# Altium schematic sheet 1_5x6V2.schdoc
size 411 x 289 mm; Name: default420x297; Symbol: default420x297; Device: default420x297; Size: "A3"; Id: /; File: 5x6V2; Sheet: /; @Page No: 1; @Page Count: 2; @Schematic Name: 5x6V2; @Project Name: 5x6V2_Left; @Board Name: 5x6V2; @Update Date: 2025-07-02; @Create Time: 08:47:11; @Update Time: 22:16:19; @Page Name: 5x6V2; @Create Date: 2025-06-30
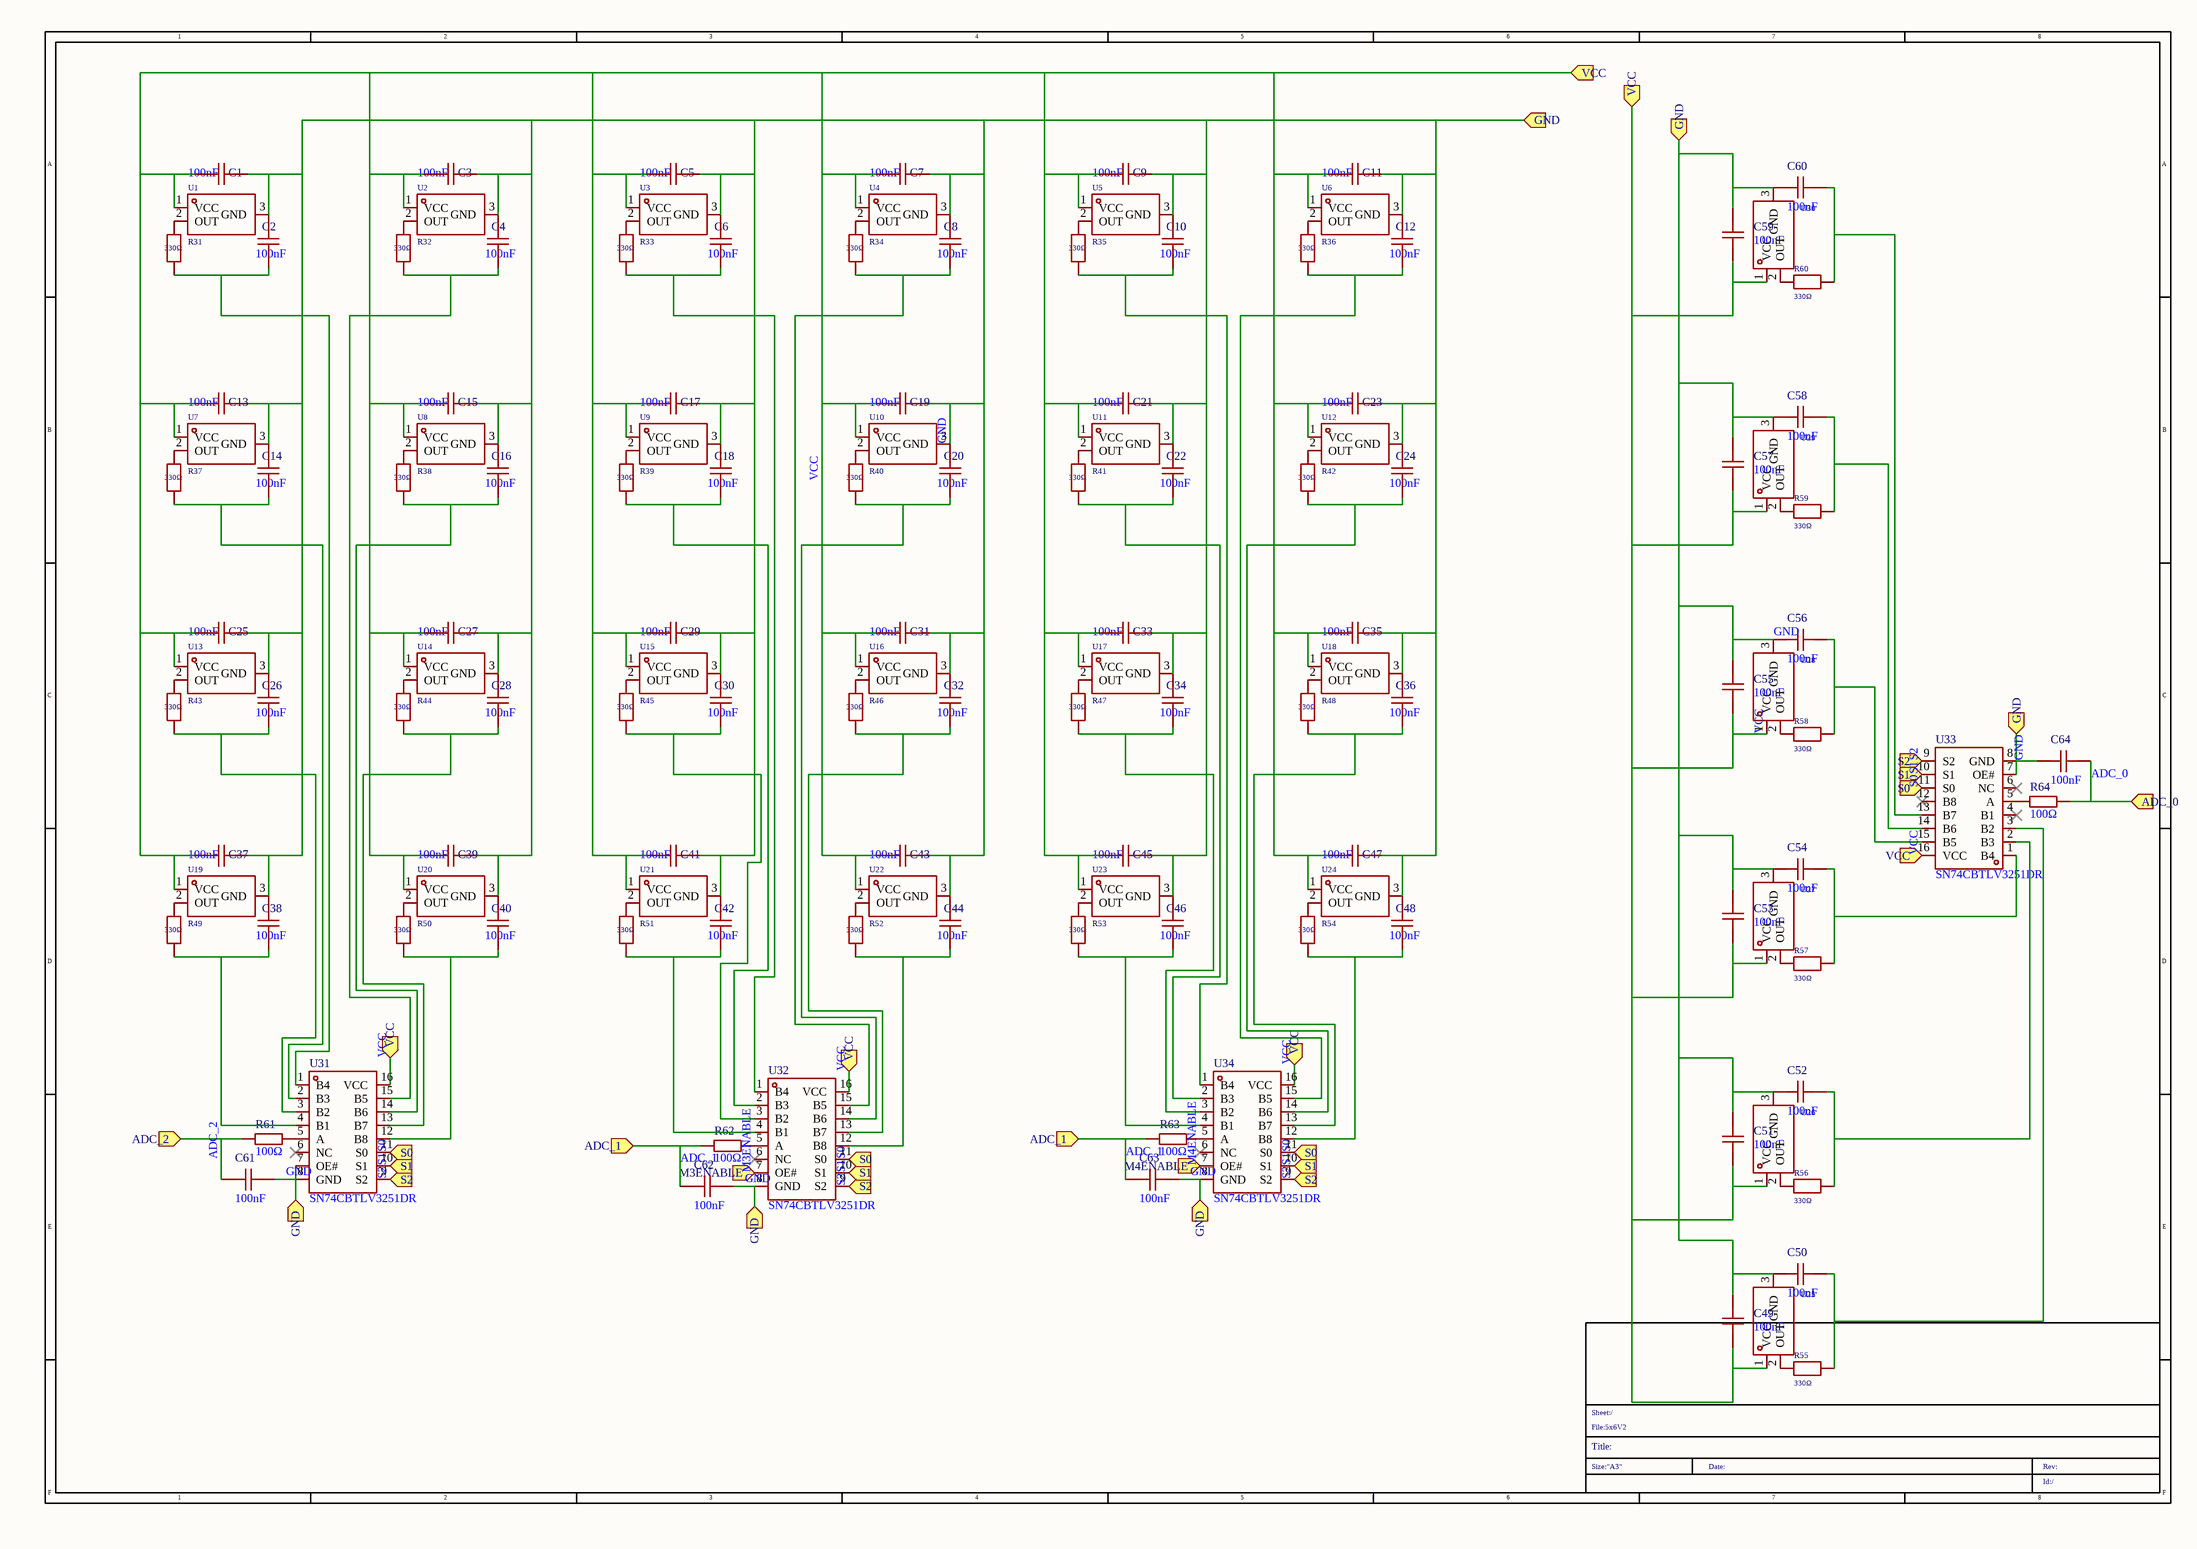
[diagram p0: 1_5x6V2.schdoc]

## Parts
C1  100nF  [C0805]
C2  100nF  [C0805]
C3  100nF  [C0805]
C4  100nF  [C0805]
C5  100nF  [C0805]
C6  100nF  [C0805]
C7  100nF  [C0805]
C8  100nF  [C0805]
C9  100nF  [C0805]
C10  100nF  [C0805]
C11  100nF  [C0805]
C12  100nF  [C0805]
C13  100nF  [C0805]
C14  100nF  [C0805]
C15  100nF  [C0805]
C16  100nF  [C0805]
C17  100nF  [C0805]
C18  100nF  [C0805]
C19  100nF  [C0805]
C20  100nF  [C0805]
C21  100nF  [C0805]
C22  100nF  [C0805]
C23  100nF  [C0805]
C24  100nF  [C0805]
C25  100nF  [C0805]
C26  100nF  [C0805]
C27  100nF  [C0805]
C28  100nF  [C0805]
C29  100nF  [C0805]
C30  100nF  [C0805]
C31  100nF  [C0805]
C32  100nF  [C0805]
C33  100nF  [C0805]
C34  100nF  [C0805]
C35  100nF  [C0805]
C36  100nF  [C0805]
C37  100nF  [C0805]
C38  100nF  [C0805]
C39  100nF  [C0805]
C40  100nF  [C0805]
C41  100nF  [C0805]
C42  100nF  [C0805]
C43  100nF  [C0805]
C44  100nF  [C0805]
C45  100nF  [C0805]
C46  100nF  [C0805]
C47  100nF  [C0805]
C48  100nF  [C0805]
C49  100nF  [C0805]
C50  100nF  [C0805]
C51  100nF  [C0805]
C52  100nF  [C0805]
C53  100nF  [C0805]
C54  100nF  [C0805]
C55  100nF  [C0805]
C56  100nF  [C0805]
C57  100nF  [C0805]
C58  100nF  [C0805]
C59  100nF  [C0805]
C60  100nF  [C0805]
C61  100nF  [C0805]
C62  100nF  [C0805]
C63  100nF  [C0805]
C64  100nF  [C0805]
R31  330Ω  [R1206]
R32  330Ω  [R1206]
R33  330Ω  [R1206]
R34  330Ω  [R1206]
R35  330Ω  [R1206]
R36  330Ω  [R1206]
R37  330Ω  [R1206]
R38  330Ω  [R1206]
R39  330Ω  [R1206]
R40  330Ω  [R1206]
R41  330Ω  [R1206]
R42  330Ω  [R1206]
R43  330Ω  [R1206]
R44  330Ω  [R1206]
R45  330Ω  [R1206]
R46  330Ω  [R1206]
R47  330Ω  [R1206]
R48  330Ω  [R1206]
R49  330Ω  [R1206]
R50  330Ω  [R1206]
R51  330Ω  [R1206]
R52  330Ω  [R1206]
R53  330Ω  [R1206]
R54  330Ω  [R1206]
R55  330Ω  [R1206]
R56  330Ω  [R1206]
R57  330Ω  [R1206]
R58  330Ω  [R1206]
R59  330Ω  [R1206]
R60  330Ω  [R1206]
R61  100Ω  [R0805]
R62  100Ω  [R0805]
R63  100Ω  [R0805]
R64  100Ω  [R0805]
U1  DRV5053VAQDBZR  [SOT-23-3_L2.9-W1.3-P1.90-LS2.4-BR]  (value not drawn)
U2  DRV5053VAQDBZR  [SOT-23-3_L2.9-W1.3-P1.90-LS2.4-BR]  (value not drawn)
U3  DRV5053VAQDBZR  [SOT-23-3_L2.9-W1.3-P1.90-LS2.4-BR]  (value not drawn)
U4  DRV5053VAQDBZR  [SOT-23-3_L2.9-W1.3-P1.90-LS2.4-BR]  (value not drawn)
U5  DRV5053VAQDBZR  [SOT-23-3_L2.9-W1.3-P1.90-LS2.4-BR]  (value not drawn)
U6  DRV5053VAQDBZR  [SOT-23-3_L2.9-W1.3-P1.90-LS2.4-BR]  (value not drawn)
U7  DRV5053VAQDBZR  [SOT-23-3_L2.9-W1.3-P1.90-LS2.4-BR]  (value not drawn)
U8  DRV5053VAQDBZR  [SOT-23-3_L2.9-W1.3-P1.90-LS2.4-BR]  (value not drawn)
U9  DRV5053VAQDBZR  [SOT-23-3_L2.9-W1.3-P1.90-LS2.4-BR]  (value not drawn)
U10  DRV5053VAQDBZR  [SOT-23-3_L2.9-W1.3-P1.90-LS2.4-BR]  (value not drawn)
U11  DRV5053VAQDBZR  [SOT-23-3_L2.9-W1.3-P1.90-LS2.4-BR]  (value not drawn)
U12  DRV5053VAQDBZR  [SOT-23-3_L2.9-W1.3-P1.90-LS2.4-BR]  (value not drawn)
U13  DRV5053VAQDBZR  [SOT-23-3_L2.9-W1.3-P1.90-LS2.4-BR]  (value not drawn)
U14  DRV5053VAQDBZR  [SOT-23-3_L2.9-W1.3-P1.90-LS2.4-BR]  (value not drawn)
U15  DRV5053VAQDBZR  [SOT-23-3_L2.9-W1.3-P1.90-LS2.4-BR]  (value not drawn)
U16  DRV5053VAQDBZR  [SOT-23-3_L2.9-W1.3-P1.90-LS2.4-BR]  (value not drawn)
U17  DRV5053VAQDBZR  [SOT-23-3_L2.9-W1.3-P1.90-LS2.4-BR]  (value not drawn)
U18  DRV5053VAQDBZR  [SOT-23-3_L2.9-W1.3-P1.90-LS2.4-BR]  (value not drawn)
U19  DRV5053VAQDBZR  [SOT-23-3_L2.9-W1.3-P1.90-LS2.4-BR]  (value not drawn)
U20  DRV5053VAQDBZR  [SOT-23-3_L2.9-W1.3-P1.90-LS2.4-BR]  (value not drawn)
U21  DRV5053VAQDBZR  [SOT-23-3_L2.9-W1.3-P1.90-LS2.4-BR]  (value not drawn)
U22  DRV5053VAQDBZR  [SOT-23-3_L2.9-W1.3-P1.90-LS2.4-BR]  (value not drawn)
U23  DRV5053VAQDBZR  [SOT-23-3_L2.9-W1.3-P1.90-LS2.4-BR]  (value not drawn)
U24  DRV5053VAQDBZR  [SOT-23-3_L2.9-W1.3-P1.90-LS2.4-BR]  (value not drawn)
U25  DRV5053VAQDBZR  [SOT-23-3_L2.9-W1.3-P1.90-LS2.4-BR]  (value not drawn)
U26  DRV5053VAQDBZR  [SOT-23-3_L2.9-W1.3-P1.90-LS2.4-BR]  (value not drawn)
U27  DRV5053VAQDBZR  [SOT-23-3_L2.9-W1.3-P1.90-LS2.4-BR]  (value not drawn)
U28  DRV5053VAQDBZR  [SOT-23-3_L2.9-W1.3-P1.90-LS2.4-BR]  (value not drawn)
U29  DRV5053VAQDBZR  [SOT-23-3_L2.9-W1.3-P1.90-LS2.4-BR]  (value not drawn)
U30  DRV5053VAQDBZR  [SOT-23-3_L2.9-W1.3-P1.90-LS2.4-BR]  (value not drawn)
U31  SN74CBTLV3251DR  [SOIC-16_L9.9-W3.9-P1.27-LS6.0-BL]
U32  SN74CBTLV3251DR  [SOIC-16_L9.9-W3.9-P1.27-LS6.0-BL]
U33  SN74CBTLV3251DR  [SOIC-16_L9.9-W3.9-P1.27-LS6.0-BL]
U34  SN74CBTLV3251DR  [SOIC-16_L9.9-W3.9-P1.27-LS6.0-BL]

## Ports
ADC_0 (in), ADC_1 (in), ADC_2 (in), GND (in), M3ENABLE (in), M4ENABLE (in), S0 (in), S1 (in), S2 (in), VCC (in)

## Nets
ADC_0: C64.1 R64.1 ; port ADC_0
ADC_1: C62.1 C63.1 R62.1 R63.1 ; port ADC_1
ADC_2: C61.1 R61.1 ; port ADC_2
GND: C1.2 C2.1 C3.2 C4.1 C5.2 C6.1 C7.2 C8.1 C9.2 C10.1 C11.2 C12.1 C13.2 C14.1 C15.2 C16.1 C17.2 C18.1 C19.2 C20.1 C21.2 C22.1 C23.2 C24.1 C25.2 C26.1 C27.2 C28.1 C29.2 C30.1 C31.2 C32.1 C33.2 C34.1 C35.2 C36.1 C37.2 C38.1 C39.2 C40.1 C41.2 C42.1 C43.2 C44.1 C45.2 C46.1 C47.2 C48.1 C49.2 C50.1 C51.2 C52.1 C53.2 C54.1 C55.2 C56.1 C57.2 C58.1 C59.2 C60.1 C61.2 C62.2 C63.2 C64.2 U1.3(GND) U2.3(GND) U3.3(GND) U4.3(GND) U5.3(GND) U6.3(GND) U7.3(GND) U8.3(GND) U9.3(GND) U10.3(GND) U11.3(GND) U12.3(GND) U13.3(GND) U14.3(GND) U15.3(GND) U16.3(GND) U17.3(GND) U18.3(GND) U19.3(GND) U20.3(GND) U21.3(GND) U22.3(GND) U23.3(GND) U24.3(GND) U25.3(GND) U26.3(GND) U27.3(GND) U28.3(GND) U29.3(GND) U30.3(GND) U31.7(OE#) U31.8(GND) U32.8(GND) U33.7(OE#) U33.8(GND) U34.8(GND) ; port GND
M3ENABLE: U32.7(OE#) ; port M3ENABLE
M4ENABLE: U34.7(OE#) ; port M4ENABLE
S0: U31.11(S0) U32.11(S0) U33.11(S0) U34.11(S0) ; port S0
S1: U31.10(S1) U32.10(S1) U33.10(S1) U34.10(S1) ; port S1
S2: U31.9(S2) U32.9(S2) U33.9(S2) U34.9(S2) ; port S2
VCC: C1.1 C3.1 C5.1 C7.1 C9.1 C11.1 C13.1 C15.1 C17.1 C19.1 C21.1 C23.1 C25.1 C27.1 C29.1 C31.1 C33.1 C35.1 C37.1 C39.1 C41.1 C43.1 C45.1 C47.1 C49.1 C51.1 C53.1 C55.1 C57.1 C59.1 U1.1(VCC) U2.1(VCC) U3.1(VCC) U4.1(VCC) U5.1(VCC) U6.1(VCC) U7.1(VCC) U8.1(VCC) U9.1(VCC) U10.1(VCC) U11.1(VCC) U12.1(VCC) U13.1(VCC) U14.1(VCC) U15.1(VCC) U16.1(VCC) U17.1(VCC) U18.1(VCC) U19.1(VCC) U20.1(VCC) U21.1(VCC) U22.1(VCC) U23.1(VCC) U24.1(VCC) U25.1(VCC) U26.1(VCC) U27.1(VCC) U28.1(VCC) U29.1(VCC) U30.1(VCC) U31.16(VCC) U32.16(VCC) U33.16(VCC) U34.16(VCC) ; port VCC
NetC2_2: C2.2 R31.1 U31.1(B4)
NetC4_2: C4.2 R32.1 U31.15(B5)
NetC6_2: C6.2 R33.1 U32.1(B4)
NetC8_2: C8.2 R34.1 U32.15(B5)
NetC10_2: C10.2 R35.1 U34.1(B4)
NetC12_2: C12.2 R36.1 U34.15(B5)
NetC14_2: C14.2 R37.1 U31.2(B3)
NetC16_2: C16.2 R38.1 U31.14(B6)
NetC18_2: C18.2 R39.1 U32.2(B3)
NetC20_2: C20.2 R40.1 U32.14(B6)
NetC22_2: C22.2 R41.1 U34.2(B3)
NetC24_2: C24.2 R42.1 U34.14(B6)
NetC26_2: C26.2 R43.1 U31.3(B2)
NetC28_2: C28.2 R44.1 U31.13(B7)
NetC30_2: C30.2 R45.1 U32.3(B2)
NetC32_2: C32.2 R46.1 U32.13(B7)
NetC34_2: C34.2 R47.1 U34.3(B2)
NetC36_2: C36.2 R48.1 U34.13(B7)
NetC38_2: C38.2 R49.1 U31.4(B1)
NetC40_2: C40.2 R50.1 U31.12(B8)
NetC42_2: C42.2 R51.1 U32.4(B1)
NetC44_2: C44.2 R52.1 U32.12(B8)
NetC46_2: C46.2 R53.1 U34.4(B1)
NetC48_2: C48.2 R54.1 U34.12(B8)
NetC50_2: C50.2 R55.1 U33.3(B2)
NetC52_2: C52.2 R56.1 U33.2(B3)
NetC54_2: C54.2 R57.1 U33.1(B4)
NetC56_2: C56.2 R58.1 U33.15(B5)
NetC58_2: C58.2 R59.1 U33.14(B6)
NetC60_2: C60.2 R60.1 U33.13(B7)
NetR31_2: R31.2 U1.2(OUT)
NetR32_2: R32.2 U2.2(OUT)
NetR33_2: R33.2 U3.2(OUT)
NetR34_2: R34.2 U4.2(OUT)
NetR35_2: R35.2 U5.2(OUT)
NetR36_2: R36.2 U6.2(OUT)
NetR37_2: R37.2 U7.2(OUT)
NetR38_2: R38.2 U8.2(OUT)
NetR39_2: R39.2 U9.2(OUT)
NetR40_2: R40.2 U10.2(OUT)
NetR41_2: R41.2 U11.2(OUT)
NetR42_2: R42.2 U12.2(OUT)
NetR43_2: R43.2 U13.2(OUT)
NetR44_2: R44.2 U14.2(OUT)
NetR45_2: R45.2 U15.2(OUT)
NetR46_2: R46.2 U16.2(OUT)
NetR47_2: R47.2 U17.2(OUT)
NetR48_2: R48.2 U18.2(OUT)
NetR49_2: R49.2 U19.2(OUT)
NetR50_2: R50.2 U20.2(OUT)
NetR51_2: R51.2 U21.2(OUT)
NetR52_2: R52.2 U22.2(OUT)
NetR53_2: R53.2 U23.2(OUT)
NetR54_2: R54.2 U24.2(OUT)
NetR55_2: R55.2 U25.2(OUT)
NetR56_2: R56.2 U26.2(OUT)
NetR57_2: R57.2 U27.2(OUT)
NetR58_2: R58.2 U28.2(OUT)
NetR59_2: R59.2 U29.2(OUT)
NetR60_2: R60.2 U30.2(OUT)
NetR61_2: R61.2 U31.5(A)
NetR62_2: R62.2 U32.5(A)
NetR63_2: R63.2 U34.5(A)
NetR64_2: R64.2 U33.5(A)

Not connected (* = marked no-connect by the designer): U31 6(NC)*; U32 6(NC)*; U33 4(B1)* 6(NC)* 12(B8)*; U34 6(NC)*

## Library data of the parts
C1-C64 = GRM21BR71H104KA01L: Manufacturer: muRata(村田); Add into BOM: yes; Tolerance: ±10%; Voltage Rating: 50V; Temperature Coefficient: X7R
R31-R60 = RT1206BRD07330RL: Manufacturer: YAGEO(国巨); Add into BOM: yes; Tolerance: ±0.1%; Power(Watts): 250mW; Temperature Coefficient: ±25ppm/℃
R61-R64 = RT0805FRD07100RL: Manufacturer: YAGEO(国巨); Add into BOM: yes; Tolerance: ±1%; Temperature Coefficient: ±25ppm/℃
U1-U30 = DRV5053VAQDBZR: Manufacturer: TI(德州仪器); Add into BOM: yes; supply voltage: 2.5V~38V
U31-U34 = SN74CBTLV3251DR: Manufacturer: TI(德州仪器); Add into BOM: yes; Number of Channels: 8; Supply Voltage: 2.3V~3.6V; On-State Resistance (Max): 58Ω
